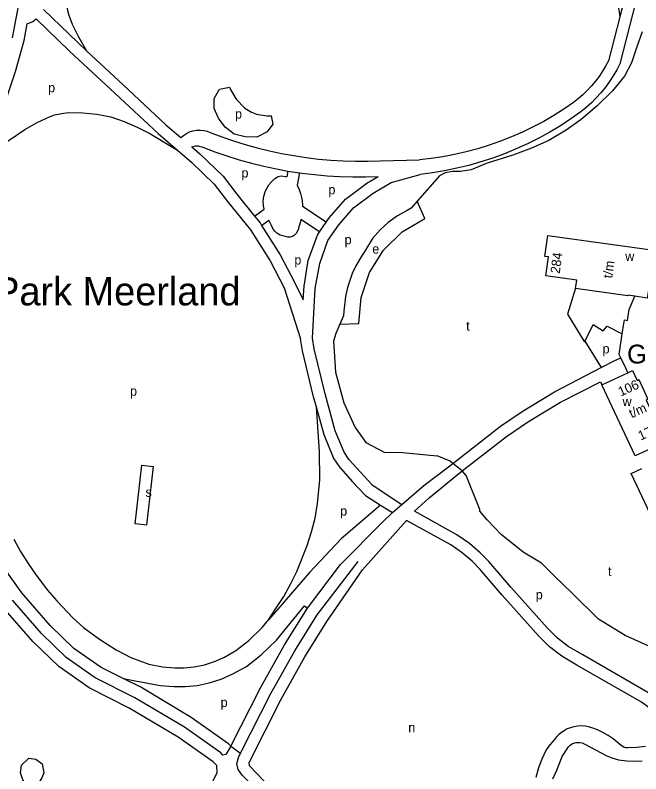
# Model space of a CAD drawing. Extents: x 155696 to 157795, y 382328 to 384028.
# Drawn here: x 156147.2 to 156412.1, y 383482.9 to 383804.3 of the extents above; entities that cross this region are included whole.
import ezdxf

# ---------------------------------------------------------------- set-up
doc = ezdxf.new("R2010")
doc.units = 0
for name, color, linetype in [('BLT_Basislijn', 7, 'Continuous'), ('BLT_Bebouwing', 7, 'Continuous'), ('BLT_Bebouwing_beschrifting', 7, 'Continuous'), ('BLT_Centroide', 7, 'Continuous'), ('BLT_Huisnummer_reeks', 7, 'Continuous'), ('BLT_Sport_parknaam', 7, 'Continuous'), ('BLT_Vlakafsluiter', 7, 'Continuous')]:
    doc.layers.add(name, color=color, linetype=linetype)

msp = doc.modelspace()

# ---------------------------------------------------------------- linework, layer by layer
at = {"layer": 'BLT_Basislijn'}
for p, q in [((156405.18, 383811.41), (156403.19, 383803.65)), ((156410.02, 383810.17), (156403.26, 383783.78)), ((156403.19, 383803.65), (156398.42, 383785.02)), ((156301.81, 383742.62), (156318.41, 383743.08)), ((156262.68, 383738.31), (156262.18, 383735.85)), ((156267.63, 383737.54), (156266.55, 383732.28)), ((156248.49, 383719.23), (156252.61, 383722.16)), ((156278.93, 383716.69), (156268.81, 383723.3)), ((156251.51, 383715.24), (156254.65, 383717.47)), ((156276.11, 383712.56), (156268.13, 383717.77)), ((156261.07, 383688.87), (156268.07, 383667.18)), ((156388.4, 383666.18), (156395.35, 383655.01)), ((156406.61, 383652.83), (156405.86, 383654.43)), ((156332.51, 383614.45), (156352.74, 383630.19)), ((156336.48, 383611.21), (156355.29, 383625.84)), ((156311.16, 383619.02), (156325.93, 383617.68)), ((156197.96, 383588.76), (156200.84, 383613.67)), ((156200.84, 383613.67), (156205.81, 383613.1)), ((156202.92, 383588.19), (156205.81, 383613.1)), ((156336.48, 383611.21), (156332.51, 383614.45)), ((156285.04, 383612.33), (156289.88, 383606.71)), ((156301.88, 383596.77), (156306.92, 383593.63)), ((156306.82, 383599.68), (156310.86, 383597.01)), ((156322.56, 383599.82), (156316.3, 383594.12)), ((156202.92, 383588.19), (156197.96, 383588.76)), ((156275.01, 383550.27), (156292.36, 383572.91))]:
    msp.add_line(p, q, dxfattribs=at)
for points in [[(156371.94, 383848), (156374.95, 383845.96), (156382.01, 383840.28), (156388.48, 383834.11), (156394.43, 383827.44), (156396.8, 383824.03), (156398.68, 383820.32), (156400.71, 383815.4), (156401.96, 383811.22), (156403.01, 383805.8), (156403.19, 383803.65)], [(156177.52, 383789.11), (156174.06, 383794.96), (156171.45, 383800.39), (156170.01, 383804.18), (156169.46, 383806.14), (156168.99, 383810.1), (156169.54, 383814.12), (156170.71, 383817.95), (156172.24, 383821.63), (156174.99, 383826.8), (156178.03, 383831.94), (156182.65, 383838.07), (156188.01, 383843.63)], [(156146.06, 383794.75), (156149.18, 383811.32)], [(156159.19, 383806.75), (156173.66, 383792.7), (156177.52, 383789.11)], [(156152.27, 383800.72), (156154.59, 383801.63), (156156.11, 383802.77)], [(156156.11, 383802.77), (156170.22, 383789.08), (156189.44, 383771.21), (156207.65, 383754.2), (156215.93, 383747.1)], [(156127.95, 383733.34), (156135.21, 383747.78), (156141.94, 383764.42), (156147.28, 383780.46), (156150.94, 383793.61), (156152.27, 383800.72)], [(156412.69, 383797.32), (156410.31, 383790.51), (156408.22, 383784.15), (156405.17, 383778.5), (156400.16, 383772.21), (156393.56, 383765.72), (156386.9, 383760.19), (156380.57, 383755.57), (156373.2, 383751.23), (156365.82, 383747.94), (156357.89, 383745.09), (156347.1, 383741.7), (156340.35, 383738.77), (156335.81, 383738.09), (156332.47, 383738.08), (156329.32, 383737.56), (156326.92, 383736.32), (156317.43, 383725.49)], [(156177.52, 383789.11), (156192.85, 383774.87), (156210.98, 383757.93), (156217.33, 383752.48)], [(156398.42, 383785.02), (156397.22, 383782.76), (156395.9, 383780.55), (156394.46, 383778.4), (156392.9, 383776.33), (156391.24, 383774.35), (156389.48, 383772.45), (156387.63, 383770.65), (156385.69, 383768.96), (156383.68, 383767.38)], [(156403.26, 383783.78), (156401.93, 383781.18), (156400.45, 383778.64), (156398.85, 383776.17), (156397.11, 383773.78), (156395.24, 383771.48), (156393.27, 383769.29), (156391.18, 383767.21), (156388.99, 383765.25), (156386.72, 383763.41)], [(156383.68, 383767.38), (156379.57, 383764.55), (156375.34, 383761.87), (156371, 383759.35), (156366.55, 383756.98), (156362, 383754.78), (156357.37, 383752.74), (156352.66, 383750.89), (156347.89, 383749.21), (156343.05, 383747.72), (156338.17, 383746.42), (156333.26, 383745.3), (156328.32, 383744.37), (156323.37, 383743.63), (156318.41, 383743.08)], [(156127.95, 383733.34), (156131.89, 383738.59), (156137.15, 383744.79), (156144.64, 383751.37), (156151.21, 383755.88), (156156.44, 383758.92), (156161.96, 383761.4), (156163.82, 383762.08), (156167.74, 383762.88), (156169.81, 383763.03), (156175.81, 383762.95), (156181.78, 383762.43), (156187.66, 383761.21), (156193.33, 383759.35), (156198.86, 383756.93), (156204.22, 383754.14), (156215.93, 383747.1)], [(156386.72, 383763.41), (156382.46, 383760.38), (156378.06, 383757.5), (156373.55, 383754.78), (156368.92, 383752.23), (156364.19, 383749.85), (156359.37, 383747.64), (156354.46, 383745.62), (156349.48, 383743.78), (156344.43, 383742.14), (156339.34, 383740.7), (156334.2, 383739.45), (156329.04, 383738.39), (156323.85, 383737.54), (156318.67, 383736.88)], [(156217.33, 383752.48), (156218.42, 383753.41), (156219.66, 383754.21), (156221.02, 383754.85), (156222.47, 383755.32), (156223.98, 383755.59), (156225.5, 383755.65), (156227, 383755.51), (156228.44, 383755.18), (156229.78, 383754.69)], [(156229.78, 383754.69), (156234.66, 383752.83), (156239.61, 383751.12), (156244.63, 383749.55), (156249.69, 383748.13), (156254.81, 383746.87), (156259.96, 383745.76), (156265.15, 383744.81), (156270.37, 383744.02), (156275.6, 383743.39), (156280.85, 383742.91), (156286.1, 383742.6), (156291.35, 383742.45), (156296.59, 383742.45), (156301.81, 383742.62)], [(156221.93, 383748.54), (156222.44, 383748.71), (156222.96, 383748.83), (156223.5, 383748.91), (156224.05, 383748.94), (156224.6, 383748.92), (156225.14, 383748.86), (156225.68, 383748.75), (156226.2, 383748.59), (156226.69, 383748.4)], [(156221.93, 383748.54), (156225.3, 383745.65), (156235.2, 383736.1), (156241.01, 383728.54), (156248.49, 383719.23)], [(156226.69, 383748.4), (156231.72, 383746.48), (156236.82, 383744.72), (156241.99, 383743.11), (156247.21, 383741.65), (156252.48, 383740.35), (156257.79, 383739.2), (156262.68, 383738.31)], [(156215.93, 383747.1), (156221.94, 383741.95), (156231.46, 383732.76), (156237.08, 383725.45), (156246.78, 383713.37), (156255.11, 383700.27), (156261.07, 383688.87)], [(156262.68, 383738.31), (156267.63, 383737.54)], [(156252.61, 383722.16), (156252.33, 383723.54), (156252.24, 383725.35), (156252.51, 383727.63), (156253.2, 383729.9), (156254.61, 383732.42), (156255.73, 383733.78), (156257.17, 383735.09), (156258.53, 383736.01), (156259.81, 383736.24), (156261.63, 383735.94), (156262.18, 383735.85)], [(156267.63, 383737.54), (156268.51, 383737.41), (156273.91, 383736.76), (156279.31, 383736.28), (156284.72, 383735.96), (156290.13, 383735.8), (156295.53, 383735.81), (156300.91, 383735.98)], [(156274.22, 383688.55), (156276.12, 383699.14), (156279.63, 383708.86), (156284.21, 383715.57), (156290.51, 383722.68), (156298.84, 383728.97), (156306.36, 383733.39), (156318.67, 383736.88)], [(156278.93, 383716.69), (156280.26, 383718.64), (156287.09, 383726.37), (156296.06, 383733.14), (156300.91, 383735.98)], [(156266.55, 383732.28), (156267.39, 383730.41), (156267.97, 383728.73), (156268.4, 383727.05), (156268.65, 383725.55), (156268.8, 383724.02), (156268.81, 383723.3)], [(156284.69, 383673.46), (156292.66, 383673.67), (156293.64, 383684.74), (156297.19, 383695.29), (156303.09, 383704.73), (156311.06, 383712.49), (156320.64, 383718.16), (156317.43, 383725.49)], [(156317.43, 383725.49), (156314.92, 383722.63), (156313.22, 383721.61), (156309.1, 383719.36), (156305.2, 383716.53), (156301.68, 383713.37), (156298.53, 383709.66), (156295.2, 383704.29), (156294.14, 383702.59), (156291.39, 383698.14), (156289.95, 383694.92), (156288.76, 383691.54), (156287.96, 383689), (156287.07, 383685.09), (156286.36, 383678.9), (156286.2, 383676.91), (156284.69, 383673.46)], [(156248.49, 383719.23), (156250.85, 383716.28), (156251.51, 383715.24)], [(156268.13, 383717.77), (156267.82, 383716.35), (156267.31, 383714.59), (156266.95, 383713.38), (156266.22, 383711.82), (156265.45, 383711.06), (156264.66, 383710.6), (156263.61, 383710.31), (156262.57, 383710.31), (156261.59, 383710.56), (156260.49, 383710.78), (156259.33, 383711.19), (156257.96, 383712.04), (156257.15, 383712.81), (156256.49, 383713.71), (156255.66, 383715.22), (156255.13, 383716.41), (156254.65, 383717.47)], [(156276.11, 383712.56), (156278.93, 383716.69)], [(156251.51, 383715.24), (156259.45, 383702.77), (156265.5, 383691.18)], [(156269.53, 383689.49), (156271.27, 383700.43), (156275.15, 383711.16), (156276.11, 383712.56)], [(156192.85, 383523.31), (156183.63, 383527.94), (156171.96, 383536.07), (156161.91, 383545.78), (156150, 383559.61), (156143.64, 383568.46), (156137.07, 383579.18), (156130.92, 383591.23), (156125.02, 383605.21), (156120.95, 383617.84), (156117.91, 383630.08), (156115.39, 383644.26), (156113.73, 383659.89), (156113.3, 383668.89), (156113.3, 383681.04), (156114.15, 383691.69), (156116.97, 383705.99), (156118.45, 383710.47)], [(156265.5, 383691.18), (156269.11, 383683.67), (156269.53, 383689.49)], [(156288.68, 383615.88), (156286.45, 383619.18), (156282.7, 383628.2), (156278.4, 383643.87), (156273.74, 383663.02), (156273.09, 383667.42), (156274.22, 383688.55)], [(156384.49, 383688.59), (156384.47, 383688.6), (156381.02, 383677.6), (156388.16, 383666.03), (156388.4, 383666.18)], [(156404.3, 383669.36), (156405.19, 383675.2), (156406.52, 383675.04), (156407.18, 383679.63), (156409.6, 383685.24)], [(156284.69, 383673.46), (156282.96, 383669.5), (156281.94, 383666.17), (156282.79, 383653.02)], [(156388.4, 383666.18), (156388.53, 383666.35), (156391.96, 383673.27), (156396.21, 383670.63), (156397.86, 383672.62), (156404.3, 383669.36)], [(156403.65, 383659.14), (156402.96, 383660.62), (156404.3, 383669.36)], [(156274.76, 383638.22), (156273.56, 383642.61), (156268.83, 383662.06), (156268.07, 383667.18)], [(156395.35, 383655.01), (156400.79, 383657.85), (156403.65, 383659.14)], [(156405.86, 383654.43), (156403.65, 383659.14)], [(156361.84, 383636.38), (156375.64, 383644.74), (156395.35, 383655.01)], [(156282.79, 383653.02), (156286.31, 383640.14), (156291.15, 383629.59), (156295.69, 383623.25), (156303.37, 383619.18)], [(156364.54, 383632.17), (156378.1, 383640.38), (156395.07, 383648.97), (156395.68, 383647.76)], [(156254.44, 383548.16), (156257.57, 383552.96), (156260.93, 383558.08), (156263.79, 383563.21), (156266.41, 383568.58), (156270.81, 383579.67), (156272.66, 383585.39), (156274.21, 383591.25), (156275.23, 383597.47), (156276.17, 383607.48), (156276.07, 383619.43), (156274.76, 383638.22)], [(156285.04, 383612.33), (156282.02, 383616.8), (156277.96, 383626.57), (156274.76, 383638.22)], [(156352.74, 383630.19), (156361.84, 383636.38)], [(156355.29, 383625.84), (156364.54, 383632.17)], [(156303.37, 383619.18), (156311.16, 383619.02)], [(156332.51, 383614.45), (156331.43, 383615.33), (156325.93, 383617.68)], [(156232.5, 383486.42), (156230.97, 383488.02), (156216.2, 383498.42), (156195.49, 383510.79), (156178.5, 383519.33), (156165.59, 383528.32), (156154.63, 383538.91), (156142.13, 383553.42), (156135.31, 383562.92), (156128.34, 383574.29), (156121.84, 383587.01), (156115.63, 383601.72), (156111.33, 383615.1)], [(156288.68, 383615.88), (156298.2, 383605.46), (156306.82, 383599.68)], [(156310.86, 383597.01), (156320.26, 383605.05), (156331.21, 383613.44), (156332.51, 383614.45)], [(156322.56, 383599.82), (156334.26, 383609.49), (156336.48, 383611.21)], [(156442.77, 383514.77), (156444.31, 383520.66), (156442.8, 383526.27), (156439.19, 383529.96), (156432.96, 383532.91), (156426.86, 383533.93), (156416.5, 383536.57), (156405.5, 383541.48), (156394.21, 383548.48), (156383.08, 383559.38), (156375.59, 383566.72), (156370.03, 383572.17), (156362.36, 383576.82), (156353.02, 383584.27), (156347.07, 383590.57), (156343.95, 383594.16), (156344.01, 383594.88), (156338.17, 383609.36), (156336.48, 383611.21)], [(156471.55, 383536.67), (156425.5, 383572.94), (156408.1, 383610.17), (156412.6, 383612.26)], [(156289.88, 383606.71), (156295.54, 383600.83), (156301.88, 383596.77), (156285.22, 383582.47), (156271.88, 383568.17), (156258.34, 383552.67), (156254.44, 383548.16)], [(156302.69, 383589.55), (156306.92, 383593.63), (156310.86, 383597.01)], [(156430.47, 383499.95), (156426.11, 383507.22), (156423.9, 383510.21), (156421.13, 383513.08), (156415.13, 383517.4), (156387.59, 383533.31), (156381.42, 383536.88), (156376.78, 383540.43), (156372.67, 383544.65), (156357.15, 383561.94), (156347.76, 383572.84), (156344.07, 383576.59), (156339.57, 383580.51), (156334.26, 383584.17), (156316.3, 383594.12)], [(156270.9, 383553.12), (156284.92, 383571.62), (156302.69, 383589.55)], [(156279.13, 383547.42), (156294.3, 383569.4), (156312.91, 383590.29)], [(156344.08, 383569.45), (156340.65, 383572.94), (156336.5, 383576.55), (156331.63, 383579.92), (156312.91, 383590.29)], [(156146.6, 383582.39), (156149.41, 383577.09), (156152.69, 383572.05), (156156.06, 383567.11), (156160.89, 383560.72), (156164.77, 383556.2), (156171.61, 383548.96), (156176.06, 383544.92), (156182.82, 383540.01), (156189.88, 383535.43), (156196.15, 383532.25), (156203.78, 383529.37), (156209.57, 383528.27), (156214.71, 383527.88), (156218.77, 383527.88), (156223.01, 383528.28), (156227.31, 383529.14), (156231.58, 383530.51), (156235.79, 383532.36), (156240.63, 383535.12), (156246.1, 383539.36), (156251.96, 383544.99), (156254.44, 383548.16)], [(156378.64, 383532.72), (156373.45, 383536.68), (156369.01, 383541.24), (156353.4, 383558.64), (156344.08, 383569.45)], [(156238.5, 383494.62), (156236.37, 383491.04), (156235.15, 383490.88), (156234.24, 383491.83), (156218.92, 383502.61), (156197.9, 383515.17), (156181.07, 383523.64), (156168.78, 383532.19), (156158.27, 383542.35), (156146.06, 383556.51)], [(156192.85, 383523.31), (156208.52, 383520.33), (156214.41, 383519.88), (156219.14, 383519.88), (156224.17, 383520.35), (156229.32, 383521.39), (156234.42, 383523.02), (156239.39, 383525.21), (156245.08, 383528.44), (156251.34, 383533.3), (156257.87, 383539.56), (156269.65, 383554.13), (156270.9, 383553.12)], [(156238.5, 383494.62), (156251.01, 383519.27), (156261.26, 383537.57), (156270.9, 383553.12)], [(156242.59, 383491.63), (156255.42, 383516.92), (156265.57, 383535.03), (156275.01, 383550.27)], [(156246.24, 383487.77), (156259.83, 383514.57), (156269.88, 383532.49), (156279.13, 383547.42)], [(156426.13, 383497.48), (156421.94, 383504.44), (156420.07, 383506.97), (156417.84, 383509.28), (156412.41, 383513.2), (156385.09, 383528.99), (156378.64, 383532.72)], [(156238.5, 383494.62), (156237.51, 383495.64), (156221.65, 383506.81), (156200.31, 383519.56), (156192.85, 383523.31)], [(156414.13, 383494.52), (156410.41, 383494.08), (156406.61, 383493.86), (156405.83, 383493.92), (156405.12, 383494.11), (156404.45, 383494.43), (156403.81, 383494.91), (156400.43, 383497.79), (156398.3, 383499.21), (156396.1, 383500.45), (156393.77, 383501.54), (156391.38, 383502.46), (156389.99, 383502.85), (156388.5, 383503.11), (156386.95, 383503.21), (156385.34, 383503.13), (156383.76, 383502.86), (156382.32, 383502.46), (156380.99, 383501.91), (156379.63, 383501.17), (156378.49, 383500.4), (156377.46, 383499.54), (156376.45, 383498.53), (156375.57, 383497.45), (156373.53, 383495.26), (156371.99, 383493.01), (156370.18, 383489.08), (156368.76, 383485.39), (156367.6, 383481.31)], [(156374.82, 383480.78), (156376.54, 383484.42), (156378.89, 383490.21), (156381.47, 383494.36), (156382.25, 383495.1), (156383.25, 383495.71), (156384.77, 383496.17), (156386.11, 383496.21), (156387.3, 383495.97), (156388.47, 383495.43), (156390.88, 383494.14), (156397.5, 383490.6), (156399.82, 383489.69), (156402.67, 383488.89), (156406.17, 383488.35), (156409.46, 383488.26), (156412.72, 383488.48)], [(156316.43, 383391.57), (156300.51, 383408.98), (156287.59, 383425.99), (156260.6, 383461.54), (156248.76, 383476.69), (156243.34, 383482.34), (156241.64, 383484.7), (156241.09, 383487.08), (156241.73, 383489.76), (156242.59, 383491.63)], [(156301.32, 383416.17), (156291.57, 383429.02), (156264.56, 383464.59), (156252.54, 383479.96), (156246.45, 383486.32), (156246.24, 383487.77)], [(156154.83, 383409.41), (156174, 383420.05), (156186, 383426.73), (156196.05, 383434.03), (156208.41, 383444.12), (156214.17, 383450.21), (156218.83, 383456.76), (156225.37, 383468.75), (156232.76, 383483.31), (156232.5, 383486.42)]]:
    msp.add_lwpolyline(points, dxfattribs=at)
for points in [[(156237.99, 383773.76), (156238.47, 383772.55), (156240.77, 383768.79), (156244.38, 383764.97), (156247.24, 383763.18), (156249.42, 383762.34), (156253.7, 383761.75), (156255.57, 383761.64), (156256.32, 383758.17), (156253.92, 383754.9), (156249.53, 383752.59), (156244.63, 383752.72), (156239.9, 383753.97), (156236.04, 383756.85), (156233.21, 383760.76), (156231.44, 383764.81), (156231.46, 383768.99), (156233.71, 383772.94)], [(156149.9, 383486.6), (156153.01, 383489.49), (156155.97, 383489.14), (156158.57, 383487.14), (156159.35, 383483.35), (156158.5, 383481.17), (156156.58, 383478.29), (156154.2, 383478.2), (156151.53, 383478.91), (156150.4, 383480.39), (156149.38, 383483.39)]]:
    msp.add_lwpolyline(points, close=True, dxfattribs=at)
at = {"layer": 'BLT_Bebouwing'}
for p, q in [((156395.68, 383647.76), (156406.61, 383652.83)), ((156419.62, 383622.17), (156409.74, 383617.57))]:
    msp.add_line(p, q, dxfattribs=at)
for points in [[(156384.49, 383688.59), (156385.01, 383692.09), (156371.87, 383693.93), (156372.99, 383701.91), (156371.48, 383702.12), (156372.74, 383711.04), (156417.71, 383704.73)], [(156417.71, 383704.73), (156425.58, 383703.63), (156423.21, 383686.73), (156415.33, 383687.84), (156414.88, 383684.5), (156409.6, 383685.24)], [(156409.6, 383685.24), (156406.67, 383685.65), (156406.64, 383685.49), (156384.49, 383688.59)], [(156406.61, 383652.83), (156408.6, 383653.76), (156410.54, 383649.62), (156411.25, 383649.95), (156415.16, 383641.58), (156414.44, 383641.24), (156422.67, 383623.59)], [(156409.74, 383617.57), (156395.68, 383647.76)]]:
    msp.add_lwpolyline(points, dxfattribs=at)
at = {"layer": 'BLT_Vlakafsluiter'}
msp.add_line((156238.5, 383494.62), (156242.59, 383491.63), dxfattribs=at)

# ---------------------------------------------------------------- texts
at = {"layer": 'BLT_Bebouwing_beschrifting'}
msp.add_text('Gezondheidscentrum', height=8, rotation=0.5505, dxfattribs=at).set_placement((156406.36, 383656.71))
at = {"layer": 'BLT_Centroide'}
for s, p in [('p', (156161.11, 383771.65)), ('p', (156240.26, 383760.52)), ('p', (156242.99, 383735.54)), ('p', (156279.83, 383728.42)), ('p', (156286.67, 383707.24)), ('e', (156298.4, 383703.31)), ('w', (156405.54, 383700.19)), ('p', (156265.39, 383698.67)), ('t', (156338.17, 383670.66)), ('p', (156395.92, 383661.02)), ('p', (156195.81, 383643.09)), ('w', (156404.4, 383638.7)), ('s', (156202.33, 383600.24)), ('p', (156284.8, 383592.3)), ('t', (156398.23, 383566.71)), ('p', (156367.64, 383556.85)), ('p', (156234.15, 383511.23)), ('n', (156313.65, 383500.53))]:
    msp.add_text(s, height=4, dxfattribs=at).set_placement(p)
at = {"layer": 'BLT_Huisnummer_reeks'}
for s, rotation, p in [('284', 82.3925, (156377.76, 383694.67)), ('t/m', 82.3925, (156399.99, 383692.68)), ('106', 24.2925, (156403.63, 383642.72)), ('t/m', 24.2925, (156408.24, 383633.49)), ('170', 24.2925, (156412.06, 383624.05))]:
    msp.add_text(s, height=4, rotation=rotation, dxfattribs=at).set_placement(p)
at = {"layer": 'BLT_Sport_parknaam'}
msp.add_text('Park Meerland', height=12, dxfattribs=at).set_placement((156138.26, 383681.36))

doc.saveas('drawing.dxf')
